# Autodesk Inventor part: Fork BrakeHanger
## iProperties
Shininess: 64.0
Length Units: 11272
Angle Units: 11279
Time Units: 11290
Mass Units: 11283
Length Display Precision: 3
Angle Display Precision: 2
Compacted: True
Part Number: Fork BrakeHanger
Document SubType Name: Modeling
Created: 2005-03
Designer: Admin
Manufacturer: Standard
Standards Organization: Custom
Density: 1 g/cm^3
Density: 0.0
Volumn: 0.0
Area: 0.0
PropertySet Name: Model Information
Control State: 0
Master: False
Checked Out: False
Author: Admin
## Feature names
1. ExtrusionBlind1
2. ExtrusionThru1
3. Fillet1
4. ExtrusionMidplane1
5. ExtrusionBlind2
6. ExtrusionBlind3
7. Fillet2
8. Loft1
9. ExtrusionThru3
10. ExtrusionThru4
11. Fillet4
12. Fillet5
13. Fillet6
14. Fillet7
15. Hole1
16. Hole2
17. Fillet8
18. Mirror1
